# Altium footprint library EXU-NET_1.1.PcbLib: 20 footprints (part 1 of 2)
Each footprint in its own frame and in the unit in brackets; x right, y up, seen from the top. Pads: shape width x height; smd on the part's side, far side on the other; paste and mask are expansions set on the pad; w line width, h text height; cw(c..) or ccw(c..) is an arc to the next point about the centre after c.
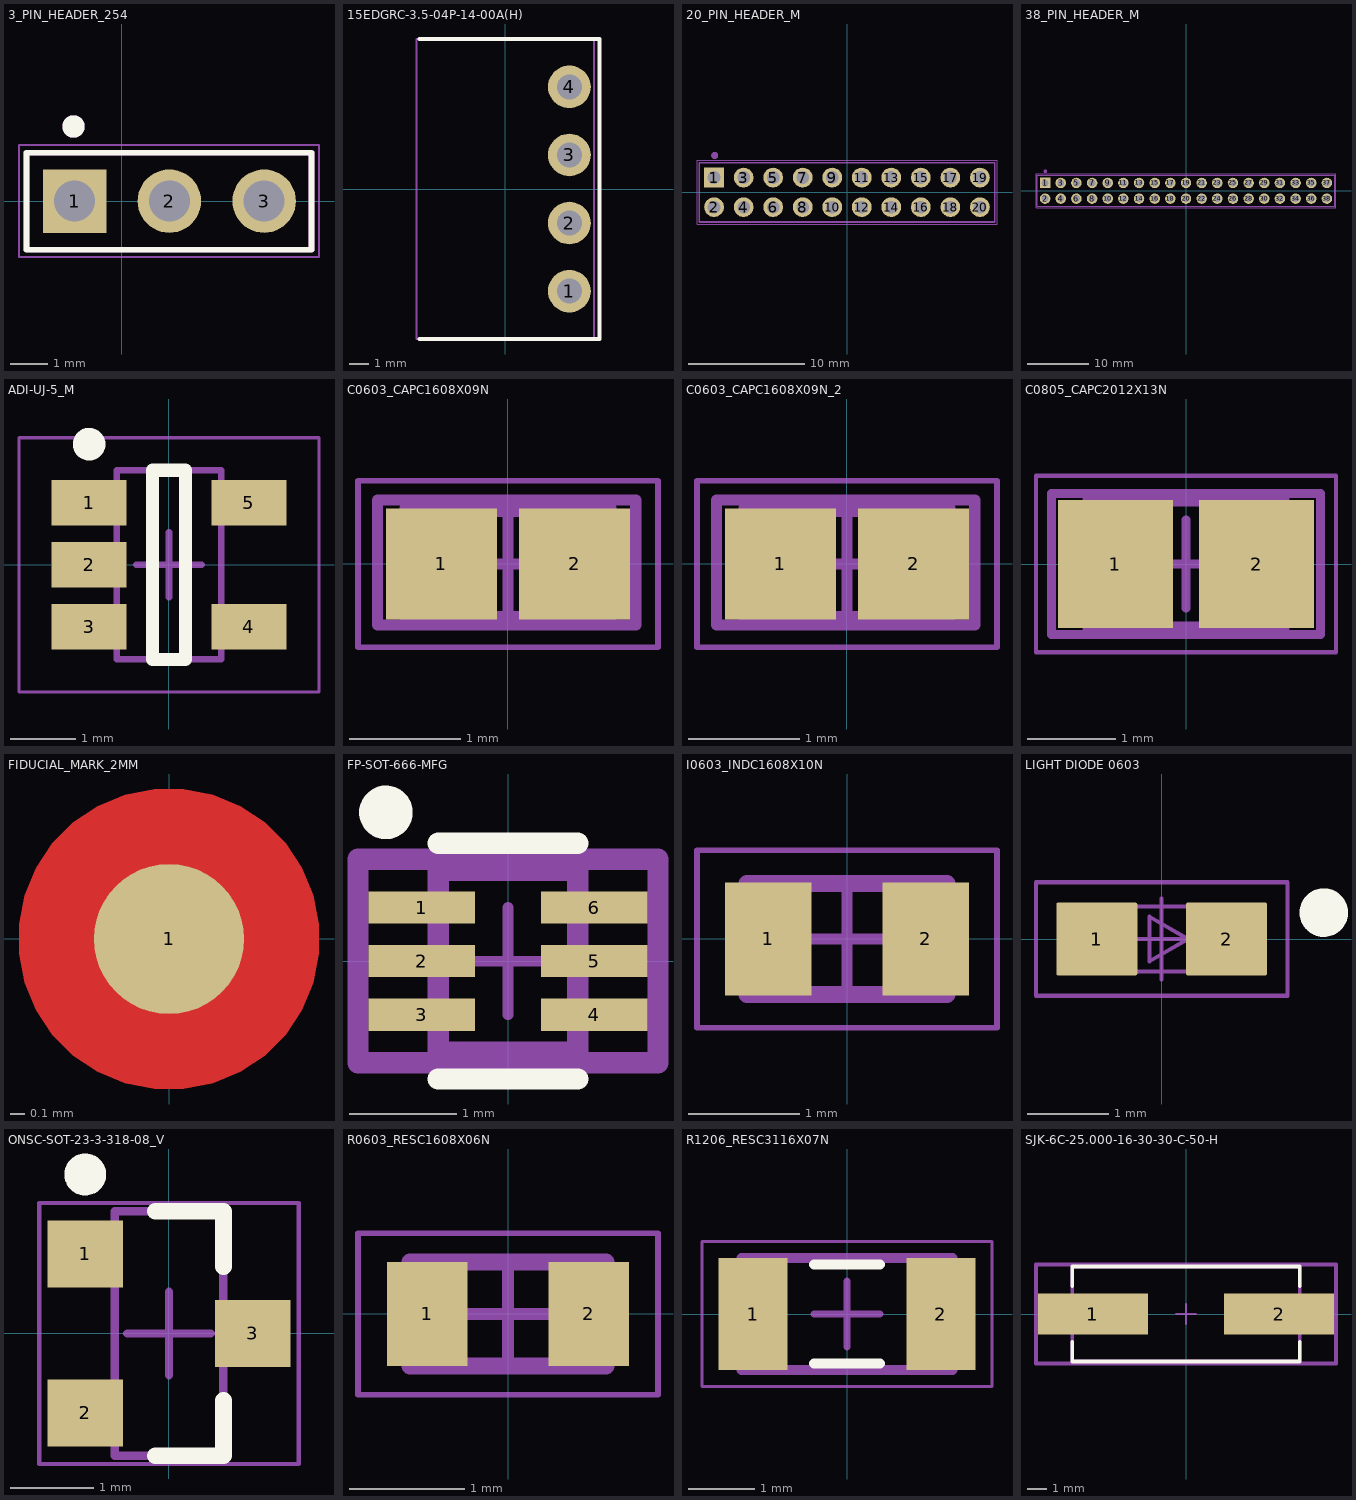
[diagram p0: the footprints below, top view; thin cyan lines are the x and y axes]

## 3_PIN_HEADER_254 [mm]
pads (3):
  rect 1.7x1.7 / inner round 1.7 / far side rect 1.7x1.7 hole 1.1: 1(-1.27,0)
  round 1.7 hole 1.1 mask+0.1: 2(1.27,0) 3(3.81,0)
Top Overlay:
  circle w0.3: c-1.3,2 r0.15
  lines w0.15: -2.56,-1.3 5.08,-1.3 5.08,1.3 -2.56,1.3 -2.56,-1.3
Mechanical 1:
  circle w0.3: c-1.3,2 r0.15
  lines w0.15: -2.56,-1.3 -2.56,1.3 5.08,1.3 5.08,-1.3 -2.56,-1.3
  text ".Designator" at -0.7,2.1 h1.27
Mechanical 15:
  lines w0.05: 0.75,0 1.75,0 ; 1.25,-0.5 1.25,0.5 ; -2.76,-1.5 -2.76,1.5 5.28,1.5 5.28,-1.5 -2.76,-1.5
3D body "Pin Header 1x2 TH Pitch 2.54mm.step": height 9.5, standoff -3.2, extent -2.54,-1.27 2.54,1.27
3D body "Pin Header 1x2 TH Pitch 2.54mm.step": height 9.5, standoff -3.2, extent -0.02,-1.27 5.06,1.27

## 15EDGRC-3.5-04P-14-00A(H) [mil]
pads (4):
  round 86.61 hole 51: 1(130,-207) 2(130,-69) 3(130,69) 4(130,207)
Top Overlay:
  lines w7.87: -173.5,304 191.16,304 191.16,-304 -173.43,-304
Top Assembly:
  lines w3.94: -180,-304 180,-304 180,304 -180,304 -180,-304
Mechanical 13:
  lines w3.94: -180,-304 180,-304 180,304 -180,304 -180,-304
3D body "Molex - 395021004 v1.step": height 280, standoff -140, extent -180,-304 180,304

## 20_PIN_HEADER_M [mm]
pads (20):
  rect 1.7x1.7 / inner round 1.7 / far side rect 1.7x1.7 hole 1.1: 1(-11.43,1.27)
  round 1.7 hole 1.1: 2(-11.43,-1.27)
  round 1.7 hole 1.1 mask+0.1: 3(-8.89,1.27) 4(-8.89,-1.27) 5(-6.35,1.27) 6(-6.35,-1.27) 7(-3.81,1.27) 8(-3.81,-1.27) 9(-1.27,1.27) 10(-1.27,-1.27) 11(1.27,1.27) 12(1.27,-1.27) 13(3.81,1.27) 14(3.81,-1.27) 15(6.35,1.27) 16(6.35,-1.27) 17(8.89,1.27) 18(8.89,-1.27) 19(11.43,1.27) 20(11.43,-1.27)
Bottom Overlay:
  circle w0.3: c-11.379,3.175 r0.15
  lines w0.15: -12.7,-2.54 12.7,-2.54 12.7,2.54 -12.7,2.54 -12.7,-2.54
Mechanical 1:
  circle w0.3: c-11.379,3.175 r0.15
  lines w0.15: -12.7,-2.54 -12.7,2.54 12.7,2.54 12.7,-2.54 -12.7,-2.54
  text ".Designator" at -4.166,2.997 h1.27
Mechanical 15:
  lines w0.05: -12.903,-2.743 12.903,-2.743 12.903,2.769 -12.903,2.769 -12.903,-2.743
3D body "PBS-3.step": height 2, standoff -9.5, extent -12.7,-2.54 -5.08,0
3D body "PBS-3.step": height 2, standoff -9.5, extent -10.16,-2.54 -2.54,0
3D body "PBS-3.step": height 2, standoff -9.5, extent -2.54,-2.54 5.08,0
3D body "PBS-3.step": height 2, standoff -9.5, extent 5.08,-2.54 12.7,0
3D body "PBS-3.step": height 2, standoff -9.5, extent 5.08,0 12.7,2.54
3D body "PBS-3.step": height 2, standoff -9.5, extent 2.54,0 10.16,2.54
3D body "PBS-3.step": height 2, standoff -9.5, extent -5.08,0 2.54,2.54
3D body "PBS-3.step": height 2, standoff -9.5, extent -12.7,0 -5.08,2.54

## 38_PIN_HEADER_M [mm]
pads (38):
  rect 1.7x1.7 / inner round 1.7 / far side rect 1.7x1.7 hole 1.1: 1(-22.86,1.27)
  round 1.7 hole 1.1: 2(-22.86,-1.27)
  round 1.7 hole 1.1 mask+0.1: 3(-20.32,1.27) 4(-20.32,-1.27) 5(-17.78,1.27) 6(-17.78,-1.27) 7(-15.24,1.27) 8(-15.24,-1.27) 9(-12.7,1.27) 10(-12.7,-1.27) 11(-10.16,1.27) 12(-10.16,-1.27) 13(-7.62,1.27) 14(-7.62,-1.27) 15(-5.08,1.27) 16(-5.08,-1.27) 17(-2.54,1.27) 18(-2.54,-1.27) 19(0,1.27) 20(0,-1.27) 21(2.54,1.27) 22(2.54,-1.27) 23(5.08,1.27) 24(5.08,-1.27) 25(7.62,1.27) 26(7.62,-1.27) 27(10.16,1.27) 28(10.16,-1.27) 29(12.7,1.27) 30(12.7,-1.27) 31(15.24,1.27) 32(15.24,-1.27) 33(17.78,1.27) 34(17.78,-1.27) 35(20.32,1.27) 36(20.32,-1.27) 37(22.86,1.27) 38(22.86,-1.27)
Bottom Overlay:
  circle w0.3: c-22.809,3.175 r0.15
  lines w0.15: -24.13,-2.54 24.13,-2.54 24.13,2.54 -24.13,2.54 -24.13,-2.54
Mechanical 1:
  circle w0.3: c-22.809,3.175 r0.15
  lines w0.15: -24.13,-2.54 -24.13,2.54 24.13,2.54 24.13,-2.54 -24.13,-2.54
  text ".Designator" at -15.596,2.997 h1.27
Mechanical 15:
  lines w0.05: -24.333,-2.743 24.333,-2.743 24.333,2.769 -24.333,2.769 -24.333,-2.743
3D body "PBS-3.step": height 2, standoff -9.5, extent 16.51,-2.54 24.13,0
3D body "PBS-3.step": height 2, standoff -9.5, extent 16.51,0 24.13,2.54
3D body "PBS-3.step": height 2, standoff -9.5, extent 13.97,-2.54 21.59,0
3D body "PBS-3.step": height 2, standoff -9.5, extent 13.97,0 21.59,2.54
3D body "PBS-3.step": height 2, standoff -9.5, extent 6.35,-2.54 13.97,0
3D body "PBS-3.step": height 2, standoff -9.5, extent 6.35,0 13.97,2.54
3D body "PBS-3.step": height 2, standoff -9.5, extent -1.27,-2.54 6.35,0
3D body "PBS-3.step": height 2, standoff -9.5, extent -1.27,0 6.35,2.54
3D body "PBS-3.step": height 2, standoff -9.5, extent -8.89,-2.54 -1.27,0
3D body "PBS-3.step": height 2, standoff -9.5, extent -8.89,0 -1.27,2.54
3D body "PBS-3.step": height 2, standoff -9.5, extent -16.51,-2.54 -8.89,0
3D body "PBS-3.step": height 2, standoff -9.5, extent -16.51,0 -8.89,2.54
3D body "PBS-3.step": height 2, standoff -9.5, extent -24.13,-2.54 -16.51,0
3D body "PBS-3.step": height 2, standoff -9.5, extent -24.13,0 -16.51,2.54

## ADI-UJ-5_M [mm]
pads (5):
  rect 1.15x0.7 smd mask+0: 1(-1.225,0.95) 2(-1.225,0) 3(-1.225,-0.95)
  rect 1.15x0.7 smd: 4(1.225,-0.95) 5(1.225,0.95)
Top Overlay:
  circle w0.25: c-1.225,1.85 r0.125
  lines w0.2: -0.25,-1.45 -0.25,1.45 0.25,1.45 0.25,-1.45 -0.25,-1.45
Mechanical 13:
  lines w0.1: -0.8,-1.45 0.8,-1.45 0.8,1.45 -0.8,1.45 -0.8,-1.45
Mechanical 15:
  lines w0.05: -2.3,-1.95 2.3,-1.95 2.3,1.95 -2.3,1.95 -2.3,-1.95
  lines w0.1: -0.5,0 0.5,0 ; 0,-0.5 0,0.5
3D body: height 1, standoff 0, extent -0.8,-1.45 0.8,1.45

## C0603_CAPC1608X09N [mm]
pads (2):
  rect 1x1 smd: 1(-0.6,0) 2(0.6,0)
Mechanical 1:
  lines w0.15: -0.9,-0.5 0.9,-0.5 0.9,0.5 -0.9,0.5 -0.9,-0.5
  text ".Designator" at -1,-0.4 h1.27
Mechanical 2:
  lines w0.1: -1.175,-0.55 -1.175,0.575 1.15,0.575 1.15,-0.55 -1.175,-0.55
Mechanical 15:
  lines w0.05: -1.35,-0.75 1.35,-0.75 1.35,0.75 -1.35,0.75 -1.35,-0.75
  lines w0.1: -0.5,0 0.5,0 ; 0,-0.5 0,0.5
3D body "CAPC1608X09N.step": height 0.95, standoff 0, extent -0.9,-0.5 0.9,0.5

## C0603_CAPC1608X09N_2 [mm]
pads (2):
  rect 1x1 smd: 1(-0.6,0) 2(0.6,0)
Mechanical 1:
  lines w0.15: -0.9,-0.5 -0.9,0.5 0.9,0.5 0.9,-0.5 -0.9,-0.5
Mechanical 2:
  lines w0.1: -1.175,-0.55 1.15,-0.55 1.15,0.575 -1.175,0.575 -1.175,-0.55
Mechanical 15:
  lines w0.05: -1.35,-0.75 -1.35,0.75 1.35,0.75 1.35,-0.75 -1.35,-0.75
  lines w0.1: -0.5,0 0.5,0 ; 0,-0.5 0,0.5
3D body "CAPC1608X09N.step": height 0.95, standoff 0, extent -0.9,-0.5 0.9,0.5

## C0805_CAPC2012X13N [mm]
pads (2):
  rect 1.3x1.45 smd: 1(-0.8,0) 2(0.8,0)
Mechanical 1:
  lines w0.15: -1.1,-0.725 1.1,-0.725 1.1,0.725 -1.1,0.725 -1.1,-0.725
  text ".Designator" at -1.2,-0.4 h1.27
Mechanical 2:
  lines w0.1: -1.525,-0.8 1.525,-0.8 1.525,0.8 -1.525,0.8 -1.525,-0.8
Mechanical 15:
  lines w0.05: -1.7,-1 1.7,-1 1.7,1 -1.7,1 -1.7,-1
  lines w0.1: -0.5,0 0.5,0 ; 0,-0.5 0,0.5
3D body "CAPC2012X13N.step": height 1.27, standoff 0, extent -1.1,-0.725 1.1,0.725

## FIDUCIAL_MARK_2MM [mil]
pads (1):
  round 40 smd paste+8.28 mask+20: 1(0,0)
Top Layer:
  pour cut-out: 0,-40 -3.94,-40 -11.67,-38.46 -18.95,-35.45 -25.5,-31.07 -31.07,-25.5 -35.45,-18.95 -38.46,-11.67 -40,-3.94 -40,0 -40,3.94 -38.46,11.67 -35.45,18.95 -31.07,25.5 -25.5,31.07 -18.95,35.45 -11.67,38.46 -3.94,40 0,40 3.94,40 11.67,38.46 18.95,35.45 25.5,31.07 31.07,25.5 35.45,18.95 38.46,11.67 40,3.94 40,0 40,-3.94 38.46,-11.67 35.45,-18.95 31.07,-25.5 25.5,-31.07 18.95,-35.45 11.67,-38.46 3.94,-40

## FP-SOT-666-MFG [mm]
pads (6):
  rect 0.99x0.3 smd paste+0 mask+0: 1(-0.805,0.5) 2(-0.805,0) 3(-0.805,-0.5) 4(0.805,-0.5) 5(0.805,0) 6(0.805,0.5)
Top Overlay:
  circle w0.25: c-1.139,1.388 r0.125
  lines w0.2: -0.65,-1.1 0.65,-1.1 ; -0.65,1.1 0.65,1.1
Top 3D Body:
  lines w0.2: -0.65,-0.85 -0.65,0.85 0.65,0.85 0.65,-0.85 -0.65,-0.85
Top Assembly:
  lines w0.2: -1.4,-0.95 -1.4,0.95 1.4,0.95 1.4,-0.95 -1.4,-0.95
  text ".Designator" at 0,0.188 h1
Top Component Center:
  lines w0.1: -0.5,0 0.5,0 ; 0,-0.5 0,0.5
3D body "Diode_STMicroelectronics_DSILC6-4P6_eec.STEP": height 0.25, standoff 0, extent -1.4,-0.95 1.4,0.95

## I0603_INDC1608X10N [mm]
pads (2):
  rect 0.78x1.02 smd: 1(-0.71,0) 2(0.71,0)
Mechanical 1:
  lines w0.15: -0.9,-0.5 0.9,-0.5 0.9,0.5 -0.9,0.5 -0.9,-0.5
Mechanical 15:
  lines w0.05: -1.35,-0.8 1.35,-0.8 1.35,0.8 -1.35,0.8 -1.35,-0.8
  lines w0.1: -0.5,0 0.5,0 ; 0,-0.5 0,0.5
3D body "INDC1608X10N.step": height 1, standoff 0, extent -0.9,-0.5 0.9,0.5

## LIGHT DIODE 0603 [mm]
pads (2):
  rrect5% 1x0.9 smd mask+0.07: 1(-0.8,0) 2(0.8,0)
Top Overlay:
  circle w0.3: c2,0.325 r0.15
Mechanical 1:
  lines w0.05: -0.5,0 0.5,0 ; 0,-0.5 0,0.5 ; -1.55,-0.7 -1.55,0.7 1.55,0.7 1.55,-0.7 -1.55,-0.7
Top Assembly:
  lines w0.05: 0.325,-0.275 0.325,0 ; 0.325,0.275 0.325,0 ; 0.325,0 -0.15,-0.275 -0.15,0 -0.15,0.275 0.325,0 ; -0.9,-0.4 -0.9,0.4 0.9,0.4 0.9,-0.4 -0.9,-0.4
Mechanical 9:
  text ".MARK" at -1.778,-0.354 h1.2
3D body: height 0.76, standoff 0.75, extent 0,-0.225 0.425,0.225
3D body "KPT-1608.STEP": height 0.75, standoff 0, extent -0.8,-0.4 0.8,0.4

## ONSC-SOT-23-3-318-08_V [mm]
pads (3):
  rect 0.9x0.8 smd: 1(-1,0.95) 2(-1,-0.95) 3(1,0)
Top Overlay:
  circle w0.25: c-1,1.9 r0.125
  lines w0.2: -0.165,-1.46 0.65,-1.46 0.65,-0.8 ; -0.165,1.46 0.65,1.46 0.65,0.8
Mechanical 13:
  lines w0.1: -0.65,-1.46 -0.65,1.46 0.65,1.46 0.65,-1.46 -0.65,-1.46
Mechanical 15:
  lines w0.05: -1.55,-1.56 -1.55,1.56 1.55,1.56 1.55,-1.56 -1.55,-1.56
  lines w0.1: -0.5,0 0.5,0 ; 0,-0.5 0,0.5
3D body: height 1.11, standoff 0.01, extent -0.65,-1.46 0.65,1.46

## R0603_RESC1608X06N [mm]
pads (2):
  rect 0.7x0.9 smd: 1(-0.7,0) 2(0.7,0)
Mechanical 1:
  text ".Designator" at -1.2,0.7 h1.27
Mechanical 2:
  lines w0.15: -0.85,-0.45 0.85,-0.45 0.85,0.45 -0.85,0.45 -0.85,-0.45
Mechanical 15:
  lines w0.05: -1.3,-0.7 1.3,-0.7 1.3,0.7 -1.3,0.7 -1.3,-0.7
  lines w0.1: -0.45,0 0.45,0 ; 0,-0.45 0,0.45
3D body "RESC1608X06N.step": height 0.55, standoff 0, extent -0.85,-0.45 0.85,0.45

## R1206_RESC3116X07N [mm]
pads (2):
  rect 1.05x1.7 smd: 1(-1.425,0) 2(1.425,0)
Top Overlay:
  lines w0.15: -0.5,-0.75 0.5,-0.75 ; -0.5,0.75 0.5,0.75
Mechanical 1:
  text ".Designator" at -1.5,-0.3 h1.27
Mechanical 2:
  lines w0.15: -1.6,-0.85 1.6,-0.85 1.6,0.85 -1.6,0.85 -1.6,-0.85
Mechanical 15:
  lines w0.05: -2.2,-1.1 2.2,-1.1 2.2,1.1 -2.2,1.1 -2.2,-1.1
  lines w0.1: -0.5,0 0.5,0 ; 0,-0.5 0,0.5
3D body "RESC3116X07N.step": height 0.65, standoff 0, extent -1.6,-0.85 1.6,0.85

## SJK-6C-25.000-16-30-30-C-50-H [mm]
pads (2):
  rect 5.6x2.1 smd paste+0 mask+0: 1(-4.75,0) 2(4.75,0)
Top Overlay:
  lines w0.2: -5.8,-1.425 -5.8,-2.425 5.8,-2.425 5.8,-1.425 ; -5.8,1.425 -5.8,2.425 5.8,2.425 5.8,1.425
Top 3D Body:
  lines w0.2: -7.65,-2.525 -7.65,2.525 7.65,2.525 7.65,-2.525 -7.65,-2.525
Top Assembly:
  lines w0.2: -7.65,-2.525 -7.65,2.525 7.65,2.525 7.65,-2.525 -7.65,-2.525
  text ".Designator" at 0,0.188 h1
Mechanical 13:
  lines w0.2: -5.8,-2.425 -5.8,2.425 5.8,2.425 5.8,-2.425 -5.8,-2.425
Top Component Center:
  lines w0.1: -0.5,0 0.5,0 ; 0,-0.5 0,0.5
3D body "Crys_Abracon_ABLS2-6_000MHZ-D4Y-T_eec.STEP": height 3.3, standoff 0, extent -6.35,-2.35 6.35,2.35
